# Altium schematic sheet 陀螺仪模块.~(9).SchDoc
size A4
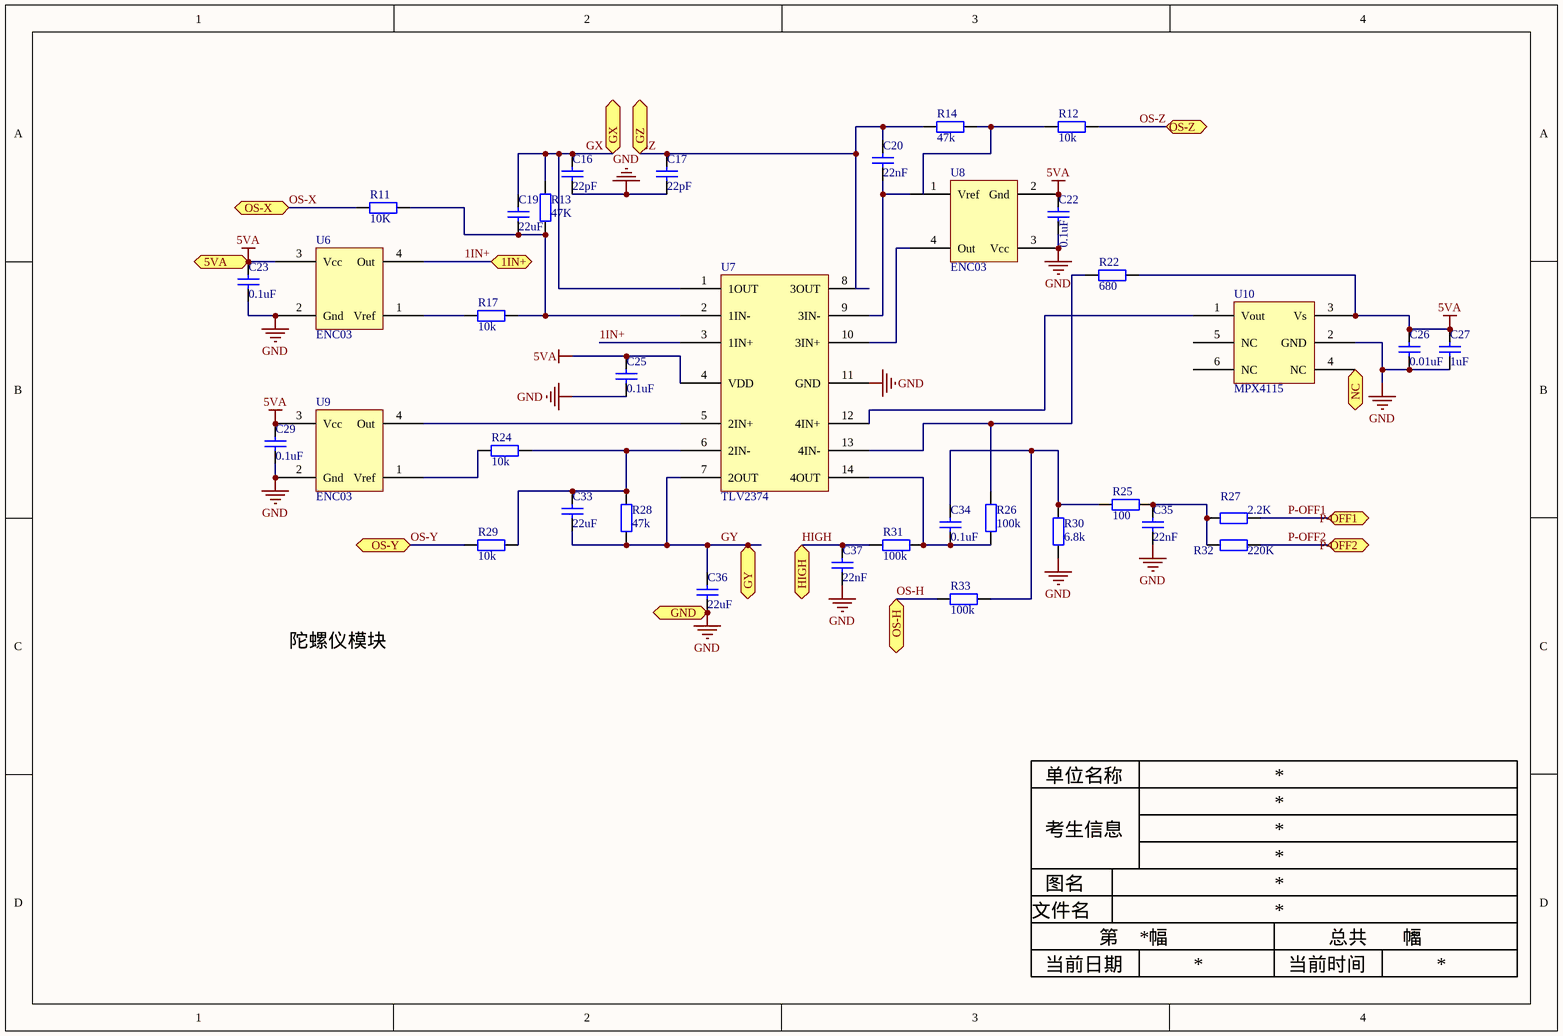
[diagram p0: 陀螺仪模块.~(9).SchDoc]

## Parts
C16  value 22pF  [RAD-0.3]  (hidden comment: Cap)
C17  value 22pF  [RAD-0.3]  (hidden comment: Cap)
C19  value 22uF  [RAD-0.3]  (hidden comment: Cap)
C20  value 22nF  [RAD-0.3]  (hidden comment: Cap)
C22  value 0.1uF  [RAD-0.3]  (hidden comment: Cap)
C23  value 0.1uF  [RAD-0.3]  (hidden comment: Cap)
C25  value 0.1uF  [RAD-0.3]  (hidden comment: Cap)
C26  value 0.01uF  [RAD-0.3]  (hidden comment: Cap)
C27  value 1uF  [RAD-0.3]  (hidden comment: Cap)
C29  value 0.1uF  [RAD-0.3]  (hidden comment: Cap)
C33  value 22uF  [RAD-0.3]  (hidden comment: Cap)
C34  value 0.1uF  [RAD-0.3]  (hidden comment: Cap)
C35  value 22nF  [RAD-0.3]  (hidden comment: Cap)
C36  value 22uF  [RAD-0.3]  (hidden comment: Cap)
C37  value 22nF  [RAD-0.3]  (hidden comment: Cap)
R11  10K  [R0603]
R12  10k  [R0603]
R13  47K  [R0603]
R14  47k  [R0603]
R17  10k  [R0603]
R22  680  [R0603]
R24  10k  [R0603]
R25  100  [R0603]
R26  100k  [R0603]
R27  2.2K  [R0603]
R28  47k  [R0603]
R29  10k  [R0603]
R30  6.8k  [R0603]
R31  100k  [R0603]
R32  220K  [R0603]
R33  100k  [R0603]
U6  ENC03  [ENC03]
U7  TLV2374  [TLV 2374]
U8  ENC03  [ENC03]
U9  ENC03  [ENC03]
U10  MPX4115  [MPX4115]

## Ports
1IN+, 5VA, GND, GX, GY, GZ, HIGH, NC, OS-H, OS-X, OS-Y, OS-Z, P-OFF1, P-OFF2

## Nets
5VA: C22.2 C23.2 C25.2 C26.2 C27.2 C29.2 R22.1 U6.3(Vcc) U7.4(VDD) U8.2(Gnd) U9.3(Vcc) U10.3(Vs) ; port 5VA
GND: C16.1 C17.1 C22.1 C23.1 C25.1 C26.1 C27.1 C29.1 C35.1 C36.1 C37.1 R30.1 U6.2(Gnd) U7.11(GND) U8.3(Vcc) U9.2(Gnd) U10.2(GND) ; port GND
1IN+: U6.4(Out) U7.3(1IN+) ; port 1IN+
GX: C16.2 C19.2 R13.1 U7.1(1OUT) ; port GX
GY: C33.1 C36.2 R28.2 U7.7(2OUT) ; port GY
GZ: C17.2 C20.2 R14.1 U7.8(3OUT) ; port GZ
HIGH: C37.2 R31.1 ; port HIGH
NC: U10.4(NC) ; port NC
OS-H: R33.1 ; port OS-H
OS-X: R11.2 ; port OS-X
OS-Y: R29.2 ; port OS-Y
OS-Z: R12.2 ; port OS-Z
P-OFF1: R27.1 ; port P-OFF1
P-OFF2: R32.1 ; port P-OFF2
NetC19_1: C19.1 R11.1 R13.2 R17.1 U7.2(1IN-)
NetC20_1: C20.1 U7.9(3IN-) U8.1(Vref)
NetC33_2: C33.2 R24.1 R28.1 R29.1 U7.6(2IN-)
NetC34_1: C34.1 R26.1 R31.2 U7.14(4OUT)
NetC34_2: C34.2 R25.2 R30.2 R33.2
NetC35_2: C35.2 R25.1 R27.2 R32.2
NetR12_1: R12.1 R14.2
NetR17_2: R17.2 U6.1(Vref)
NetR22_2: R22.2 R26.2 U7.13(4IN-)
NetR24_2: R24.2 U9.1(Vref)
NetU7_5: U7.5(2IN+) U9.4(Out)
NetU7_10: U7.10(3IN+) U8.4(Out)
NetU7_12: U7.12(4IN+) U10.1(Vout)

Not connected (* = marked no-connect by the designer): U10 5(NC) 6(NC)

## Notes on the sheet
- 单位名称
- 考生信息
- 文件名
- 图名
- 当前日期
- 第      幅
- 当前时间
- 总共       幅
- Labels drawn without touching a wire or pin: 陀螺仪模块

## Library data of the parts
C16 C17 C19 C20 C22 C23 C25-C27 C29 C33-C37 = Cap: Capacitor
R11-R14 R17 R22 R24-R33 = R0603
